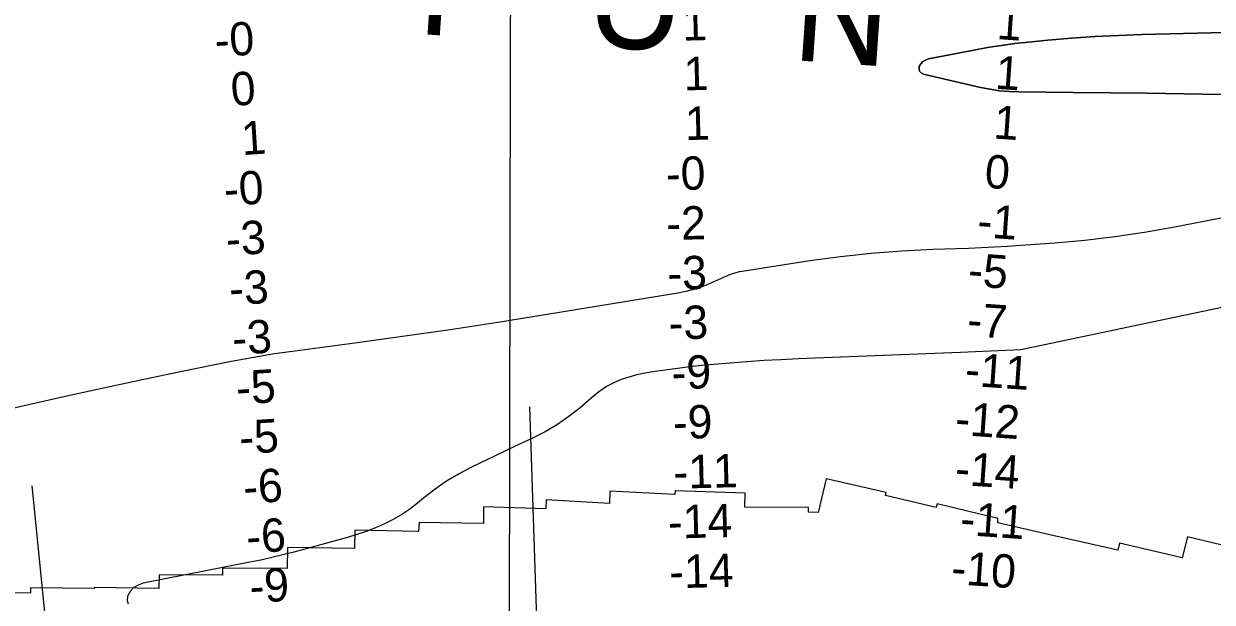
# Model space of a CAD drawing. Extents: x 3192986 to 3230865, y 867483 to 892886.
# Drawn here: x 3206675 to 3209065, y 877451 to 878614 of the extents above; entities that cross this region are included whole.
import ezdxf

# ---------------------------------------------------------------- set-up
doc = ezdxf.new("R2010")
doc.units = 0
for name, color, linetype in [('V-GRID-MAJR', 7, 'Continuous'), ('V-RIVR-IDEN', 7, 'Continuous'), ('V-RIVR-RANG', 7, 'Continuous'), ('V-RRAP-RVMT', 7, 'Continuous'), ('V-TOPO-DPTH', 7, 'Continuous'), ('V-TOPO-MINR', 7, 'Continuous')]:
    doc.layers.add(name, color=color, linetype=linetype)

msp = doc.modelspace()

# ---------------------------------------------------------------- linework, layer by layer
at = {"layer": 'V-GRID-MAJR'}
msp.add_spline([(3207642.5, 872901.1), (3207654.8, 878960.7), (3207667.2, 885023.3), (3207679.5, 891086), (3207679.5, 891089.1)], degree=3, dxfattribs=at)
at = {"layer": 'V-RIVR-RANG'}
for p, q in [((3207733.4, 876584.9), (3207693, 877844.2)), ((3206803.4, 876571.2), (3206691.8, 877685.7))]:
    msp.add_line(p, q, dxfattribs=at)
at = {"layer": 'V-RRAP-RVMT'}
for p, q in [((3208288.5, 877699.6), (3208272.6, 877632.1)), ((3208409.7, 877671.9), (3208288.5, 877699.6)), ((3207853.9, 877674.5), (3207852.7, 877650.2)), ((3207984.4, 877668.2), (3207853.9, 877674.5)), ((3207985.2, 877675.5), (3207984.4, 877668.2)), ((3208126, 877670.5), (3207985.2, 877675.5)), ((3208125.4, 877642.8), (3208126, 877670.5)), ((3208408.3, 877665.7), (3208409.7, 877671.9)), ((3207599.5, 877643), (3207599.3, 877609.6)), ((3207725.2, 877639.1), (3207599.5, 877643)), ((3207725.7, 877657.3), (3207725.2, 877639.1)), ((3207852.7, 877650.2), (3207725.7, 877657.3)), ((3208253.4, 877641.9), (3208125.4, 877642.8)), ((3208510, 877642), (3208408.3, 877665.7)), ((3208511.9, 877649.2), (3208510, 877642)), ((3208631.4, 877620.6), (3208511.9, 877649.2)), ((3208253.5, 877632.4), (3208253.4, 877641.9)), ((3208272.6, 877632.1), (3208253.5, 877632.4)), ((3208634.2, 877620.6), (3208631.4, 877620.6)), ((3208634, 877610.9), (3208634.2, 877620.6)), ((3207340.7, 877596.3), (3207340.1, 877559.8)), ((3207469, 877593.4), (3207340.7, 877596.3)), ((3207469.9, 877612), (3207469, 877593.4)), ((3207599.3, 877609.6), (3207469.9, 877612)), ((3208747.2, 877585), (3208634, 877610.9)), ((3208875.3, 877555.9), (3208747.2, 877585)), ((3209015.2, 877582.6), (3209005, 877540.6)), ((3209141.4, 877552.8), (3209015.2, 877582.6)), ((3207205.4, 877561.5), (3207204.5, 877519)), ((3207340.1, 877559.8), (3207205.4, 877561.5)), ((3208878.4, 877570), (3208875.3, 877555.9)), ((3209005, 877540.6), (3208878.4, 877570)), ((3206947.3, 877506.5), (3206946.6, 877478.9)), ((3207074.9, 877505.9), (3206947.3, 877506.5)), ((3207204.5, 877519), (3207074.9, 877520.2)), ((3207074.9, 877520.2), (3207074.9, 877505.9)), ((3206817.4, 877479.3), (3206688.5, 877480.2)), ((3206688.5, 877480.2), (3206688.7, 877469.7)), ((3206946.6, 877478.9), (3206817.3, 877480.9)), ((3206817.3, 877480.9), (3206817.4, 877479.3)), ((3206688.7, 877469.7), (3206566.2, 877472.2))]:
    msp.add_line(p, q, dxfattribs=at)
at = {"layer": 'V-TOPO-DPTH'}
for points in [[(3209228.9, 878600.5), (3208924.3, 878592.8), (3208876.8, 878591.1), (3208829.5, 878588.7), (3208782.2, 878585.4), (3208734.9, 878581.4), (3208695.9, 878577.6), (3208668.2, 878574.6), (3208640.6, 878571), (3208613.1, 878566.5), (3208585.7, 878561.6), (3208494.4, 878543.6), (3208488.5, 878541.4), (3208483.4, 878538.3), (3208479.4, 878533.9), (3208476.1, 878528.5), (3208475.7, 878523.3), (3208476.6, 878518.8), (3208479.7, 878515.5), (3208484.2, 878512.9), (3208599.3, 878486.4), (3208618.4, 878482.7), (3208637.6, 878479.7), (3208656.9, 878478.1), (3208676.4, 878477.3), (3208786, 878476.4), (3208860.3, 878475.6), (3208934.6, 878474.6), (3209008.9, 878473.4), (3209083.2, 878472)], [(3209228.9, 878600.5), (3208924.3, 878592.8), (3208876.8, 878591.1), (3208829.5, 878588.7), (3208782.2, 878585.4), (3208734.9, 878581.4), (3208695.9, 878577.6), (3208668.2, 878574.6), (3208640.6, 878571), (3208613.1, 878566.5), (3208585.7, 878561.6), (3208494.4, 878543.6), (3208488.5, 878541.4), (3208483.4, 878538.3), (3208479.4, 878533.9), (3208476.1, 878528.5), (3208475.7, 878523.3), (3208476.6, 878518.8), (3208479.7, 878515.5), (3208484.2, 878512.9), (3208599.3, 878486.4), (3208618.4, 878482.7), (3208637.6, 878479.7), (3208656.9, 878478.1), (3208676.4, 878477.3), (3208786, 878476.4), (3208860.3, 878475.6), (3208934.6, 878474.6), (3209008.9, 878473.4), (3209083.2, 878472)], [(3209109.9, 878049.5), (3208680.2, 877959), (3208649.9, 877957.6), (3208619.6, 877956.2), (3208589.2, 877954.9), (3208558.9, 877953.7), (3208232.2, 877940.6), (3208197.8, 877939), (3208163.5, 877937.1), (3208129.2, 877934.8), (3208095, 877932.1), (3208038.4, 877927.3), (3208032.5, 877926.7), (3208026.5, 877926.1), (3208020.5, 877925.4), (3208014.6, 877924.7), (3207940, 877914.7), (3207923.9, 877912), (3207907.9, 877908.5), (3207892.1, 877904.1), (3207876.6, 877898.9), (3207861.6, 877892.4), (3207847.2, 877884.9), (3207833.8, 877875.9), (3207820.9, 877865.9), (3207793.9, 877842.6), (3207771.5, 877824.9), (3207748.3, 877808.5), (3207723.7, 877794.2), (3207698.3, 877781.2), (3207672.3, 877769.1), (3207646.3, 877757), (3207620.4, 877744.7), (3207594.6, 877732.2), (3207574.1, 877722.2), (3207549.3, 877709), (3207525.2, 877694.7), (3207502.2, 877678.7), (3207479.9, 877661.5), (3207467.1, 877650.8), (3207451.4, 877638.8), (3207435.1, 877627.7), (3207418, 877617.8), (3207400.4, 877608.9), (3207382.2, 877601), (3207363.8, 877593.8), (3207345, 877587.5), (3207326, 877581.8), (3207218.3, 877552.4), (3207196.3, 877546.7), (3207174.1, 877541.3), (3207151.9, 877536.3), (3207129.6, 877531.7), (3206915, 877489.6), (3206904.8, 877485.9), (3206895.9, 877480.5), (3206889.1, 877472.8), (3206883.6, 877463.5), (3206883.1, 877455.1), (3206885, 877448.2)], [(3209109.9, 878049.5), (3208680.2, 877959), (3208649.9, 877957.6), (3208619.6, 877956.2), (3208589.2, 877954.9), (3208558.9, 877953.7), (3208232.2, 877940.6), (3208197.8, 877939), (3208163.5, 877937.1), (3208129.2, 877934.8), (3208095, 877932.1), (3208038.4, 877927.3), (3208032.5, 877926.7), (3208026.5, 877926.1), (3208020.5, 877925.4), (3208014.6, 877924.7), (3207940, 877914.7), (3207923.9, 877912), (3207907.9, 877908.5), (3207892.1, 877904.1), (3207876.6, 877898.9), (3207861.6, 877892.4), (3207847.2, 877884.9), (3207833.8, 877875.9), (3207820.9, 877865.9), (3207793.9, 877842.6), (3207771.5, 877824.9), (3207748.3, 877808.5), (3207723.7, 877794.2), (3207698.3, 877781.2), (3207672.3, 877769.1), (3207646.3, 877757), (3207620.4, 877744.7), (3207594.6, 877732.2), (3207574.1, 877722.2), (3207549.3, 877709), (3207525.2, 877694.7), (3207502.2, 877678.7), (3207479.9, 877661.5), (3207467.1, 877650.8), (3207451.4, 877638.8), (3207435.1, 877627.7), (3207418, 877617.8), (3207400.4, 877608.9), (3207382.2, 877601), (3207363.8, 877593.8), (3207345, 877587.5), (3207326, 877581.8), (3207218.3, 877552.4), (3207196.3, 877546.7), (3207174.1, 877541.3), (3207151.9, 877536.3), (3207129.6, 877531.7), (3206915, 877489.6), (3206904.8, 877485.9), (3206895.9, 877480.5), (3206889.1, 877472.8), (3206883.6, 877463.5), (3206883.1, 877455.1), (3206885, 877448.2)]]:
    msp.add_lwpolyline(points, dxfattribs=at)
at = {"layer": 'V-TOPO-MINR'}
for points in [[(3209083.2, 878472), (3209008.9, 878473.4), (3208934.6, 878474.6), (3208860.3, 878475.6), (3208786, 878476.4), (3208676.4, 878477.3), (3208656.9, 878478.1), (3208637.6, 878479.7), (3208618.4, 878482.7), (3208599.3, 878486.4), (3208484.2, 878512.9), (3208479.7, 878515.5), (3208476.6, 878518.8), (3208475.7, 878523.3), (3208476.1, 878528.5), (3208479.4, 878533.9), (3208483.4, 878538.3), (3208488.5, 878541.4), (3208494.4, 878543.6), (3208585.7, 878561.6), (3208613.1, 878566.5), (3208640.6, 878571), (3208668.2, 878574.6), (3208695.9, 878577.6), (3208734.9, 878581.4), (3208782.2, 878585.4), (3208829.5, 878588.7), (3208876.8, 878591.1), (3208924.3, 878592.8), (3209228.9, 878600.5)], [(3209086.7, 878224.2), (3208989, 878205.4), (3208929.2, 878195), (3208869.2, 878185.9), (3208809, 878179), (3208748.5, 878173.4), (3208679.5, 878168.3), (3208653.4, 878166.5), (3208627.3, 878165), (3208601.1, 878163.8), (3208574.9, 878162.7), (3208503, 878160.4), (3208441, 878157.3), (3208379.1, 878152.7), (3208317.4, 878145.9), (3208255.9, 878137.5), (3208120, 878116.6), (3208113.5, 878115.4), (3208107, 878113.8), (3208100.7, 878111.8), (3208094.5, 878109.5), (3208088.3, 878106.9), (3208082.2, 878104.3), (3208076, 878101.6), (3208069.9, 878098.9), (3208052.3, 878091.1), (3208037.2, 878085.1), (3208021.9, 878079.9), (3208006.2, 878075.9), (3207990.3, 878072.7), (3207723.8, 878029.2), (3207628.2, 878014), (3207532.5, 877999.3), (3207436.6, 877985.6), (3207340.7, 877972.3), (3207209.8, 877954.9), (3207179.3, 877950.5), (3207148.9, 877945.7), (3207118.7, 877940.3), (3207088.5, 877934.5), (3206993.8, 877915.2), (3206916.4, 877899.1), (3206839, 877882.7), (3206761.8, 877865.7), (3206684.7, 877848.3), (3206526.1, 877811.9)], [(3209109.9, 878049.5), (3208680.2, 877959), (3208649.9, 877957.6), (3208619.6, 877956.2), (3208589.2, 877954.9), (3208558.9, 877953.7), (3208232.2, 877940.6), (3208197.8, 877939), (3208163.5, 877937.1), (3208129.2, 877934.8), (3208095, 877932.1), (3208038.4, 877927.3), (3208032.5, 877926.7), (3208026.5, 877926.1), (3208020.5, 877925.4), (3208014.6, 877924.7), (3207940, 877914.7), (3207923.9, 877912), (3207907.9, 877908.5), (3207892.1, 877904.1), (3207876.6, 877898.9), (3207861.6, 877892.4), (3207847.2, 877884.9), (3207833.8, 877875.9), (3207820.9, 877865.9), (3207793.9, 877842.6), (3207771.5, 877824.9), (3207748.3, 877808.5), (3207723.7, 877794.2), (3207698.3, 877781.2), (3207672.3, 877769.1), (3207646.3, 877757), (3207620.4, 877744.7), (3207594.6, 877732.2), (3207574.1, 877722.2), (3207549.3, 877709), (3207525.2, 877694.7), (3207502.2, 877678.7), (3207479.9, 877661.5), (3207467.1, 877650.8), (3207451.4, 877638.8), (3207435.1, 877627.7), (3207418, 877617.8), (3207400.4, 877608.9), (3207382.2, 877601), (3207363.8, 877593.8), (3207345, 877587.5), (3207326, 877581.8), (3207218.3, 877552.4), (3207196.3, 877546.7), (3207174.1, 877541.3), (3207151.9, 877536.3), (3207129.6, 877531.7), (3206915, 877489.6), (3206904.8, 877485.9), (3206895.9, 877480.5), (3206889.1, 877472.8), (3206883.6, 877463.5), (3206883.1, 877455.1), (3206885, 877448.2)]]:
    msp.add_lwpolyline(points, dxfattribs=at)

# ---------------------------------------------------------------- texts
at = {"layer": 'V-RIVR-IDEN'}
msp.add_text('T   U   N   ', height=200, rotation=355.9975, dxfattribs=at).set_placement((3207417.9, 878597.6))
at = {"layer": 'V-RIVR-RANG'}
for s, rotation, p in [('1', 1.5181, (3208000.4, 878580.3)), ('1', 356, (3208630.5, 878583.8)), ('-0', 3.601, (3207060.8, 878547.4)), ('1', 1.5181, (3208003, 878480.3)), ('1', 356, (3208627.3, 878483.8)), ('0', 3.601, (3207093.4, 878449.2)), ('1', 1.5181, (3208005.6, 878380.4)), ('1', 356, (3208624.1, 878383.9)), ('1', 3.601, (3207114.4, 878350.3)), ('-0', 1.5181, (3207967.1, 878279.3)), ('0', 356, (3208606.2, 878285)), ('-0', 3.601, (3207079.6, 878248)), ('-2', 1.5181, (3207967.9, 878179.3)), ('-1', 356, (3208591.4, 878185.8)), ('-3', 3.601, (3207083.5, 878148)), ('-3', 1.5181, (3207970, 878079.3)), ('-5', 356, (3208572.6, 878087)), ('-3', 3.601, (3207089.8, 878048.2)), ('-3', 1.5181, (3207972.6, 877979.4)), ('-7', 356, (3208571, 877986.9)), ('-3', 3.601, (3207096.1, 877948.4)), ('-9', 1.5181, (3207978.6, 877879.5)), ('-11', 356, (3208566.5, 877887.1)), ('-5', 3.601, (3207103.9, 877848.7)), ('-9', 1.5181, (3207981.2, 877779.5)), ('-12', 356, (3208546.7, 877788.3)), ('-5', 3.601, (3207110.2, 877748.9)), ('-11', 1.5181, (3207982.3, 877679.5)), ('-14', 356, (3208546.4, 877688.1)), ('-6', 3.601, (3207118.1, 877649.2)), ('-14', 1.5181, (3207971.2, 877579.2)), ('-11', 356, (3208556.9, 877587.2)), ('-6', 3.601, (3207124.3, 877549.4)), ('-14', 1.5181, (3207973.8, 877479.2)), ('-10', 356, (3208538.9, 877488.3)), ('-9', 3.601, (3207130.9, 877449.6))]:
    msp.add_text(s, height=67, rotation=rotation, dxfattribs=at).set_placement(p)

doc.saveas('drawing.dxf')
